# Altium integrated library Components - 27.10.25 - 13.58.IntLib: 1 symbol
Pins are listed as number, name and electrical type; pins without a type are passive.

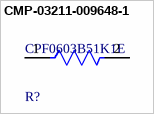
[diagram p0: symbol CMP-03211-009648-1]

## CMP-03211-009648-1
designator R?, comment CPF0603B51K1E
RES SMD 51.1KΩ 0.1% 1/16W 0603; Manufacturer: TE Connectivity; Voltage Rating: 50V; Power Rating: 0.063W; Temperature Coefficient: 25ppm/°C
footprint FP-CPF0603-IPC_C
footprint FP-CPF0603-IPC_A
footprint FP-CPF0603-MFG
footprint FP-CPF0603-IPC_B
pins: 1, 2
